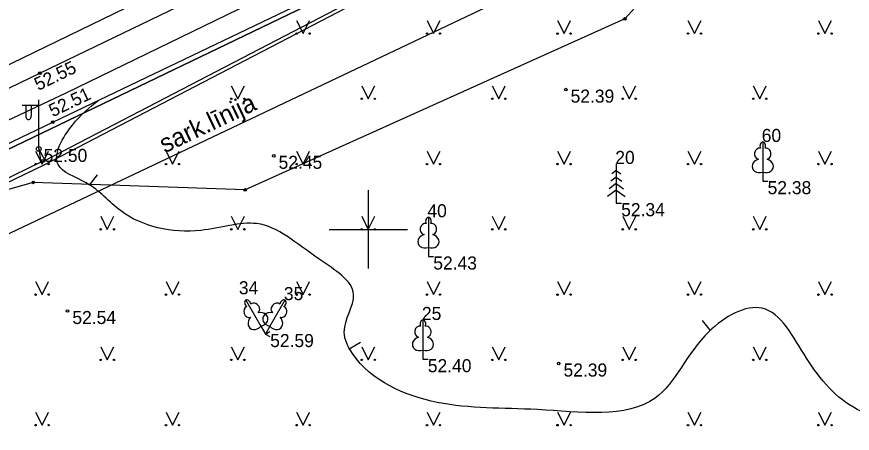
# Model space of a CAD drawing. Extents: x 619806 to 620082, y 405176 to 405386.
# Drawn here: x 619836.53 to 619868.55, y 405292.19 to 405308.14 of the extents above; entities that cross this region are included whole.
import ezdxf

# ---------------------------------------------------------------- set-up
doc = ezdxf.new("R2010")
doc.units = 0
for name, color, linetype in [('24', 7, 'Continuous'), ('APGR_SARK_####_####_#', 7, 'Continuous'), ('APGR_SARK_IZNL_TKST_#', 7, 'Continuous'), ('APGS_ELEM_####_####_#', 7, 'Continuous'), ('APGS_VADP_ZSPR_####_#', 7, 'Continuous'), ('CELI_CMAL_####_####_#', 7, 'Continuous'), ('GEOD_ELEM_####_####_#', 7, 'Continuous'), ('RAMI_UZMR_####_####_#', 7, 'Continuous'), ('RELJ_AATZ_####_TKST_#', 7, 'Continuous'), ('RELJ_ELEM_####_####_#', 7, 'Continuous'), ('RELJ_HORZ_PAMT_####_#', 7, 'Continuous'), ('ROBZ_UZMR_####_####_#', 7, 'Continuous'), ('SAKT_VADP_KABE_####_#', 7, 'Continuous'), ('TERT_DIAM_####_TKST_#', 7, 'Continuous'), ('TERT_ELEM_####_####_#', 7, 'Continuous')]:
    doc.layers.add(name, color=color, linetype=linetype)

msp = doc.modelspace()

# ---------------------------------------------------------------- linework, layer by layer
at = {"layer": '24'}
msp.add_line((619931.837, 405349.12), (619818.193, 405294.391), dxfattribs=at)
at = {"layer": 'APGR_SARK_####_####_#'}
msp.add_lwpolyline([(619818.56, 405291.467), (619964.609, 405360.731), (619976.198, 405343.424)], dxfattribs=at)
at = {"layer": 'APGS_ELEM_####_####_#'}
for p, q in [((619837.373, 405303.082), (619837.373, 405304.965)), ((619837.373, 405304.749), (619836.738, 405304.744)), ((619836.873, 405304.745), (619836.873, 405304.353)), ((619837.083, 405304.747), (619837.083, 405304.353))]:
    msp.add_line(p, q, dxfattribs=at)
msp.add_circle((619837.373, 405303.082), 0.09, dxfattribs=at)
msp.add_ellipse((619836.978, 405304.353), major_axis=(0, 0.151), ratio=0.695971, start_param=1.570796, end_param=4.712389, dxfattribs=at)
at = {"layer": 'APGS_VADP_ZSPR_####_#'}
for points in [[(619961.504, 405361.726), (619961.549, 405360.889), (619955.561, 405357.47), (619948.629, 405353.911), (619942.586, 405351.309), (619934.737, 405347.784), (619926.308, 405343.807), (619921.62, 405341.722), (619914.616, 405338.589), (619904.064, 405332.419), (619892.947, 405327.707), (619882.253, 405322.432), (619872.343, 405318.394), (619866.043, 405315.914), (619858.147, 405313.031), (619849.141, 405308.474), (619837.591, 405302.476), (619829.867, 405298.738), (619827.533, 405297.619), (619826.332, 405294.789), (619825.868, 405290.973), (619826.009, 405290.873), (619827.279, 405290.766)], [(619961.504, 405361.726), (619961.582, 405360.944), (619961.547, 405359.255), (619942.312, 405349.715), (619925.4, 405342.794), (619907.997, 405333.971), (619887.51, 405324.581), (619867.415, 405316.417), (619859.827, 405308.06), (619845.28, 405301.51), (619837.164, 405301.798), (619827.1, 405298.963), (619826.475, 405294.709), (619826.025, 405290.988), (619827.279, 405290.766)], [(619904.019, 405332.565), (619892.911, 405327.951), (619882.359, 405322.589), (619872.341, 405318.531), (619866.186, 405316.142), (619865.74, 405316.62), (619866.013, 405316.067), (619858.137, 405313.192), (619849.107, 405308.602), (619837.621, 405302.637), (619837.373, 405303.082), (619837.457, 405302.572), (619827.49, 405297.724), (619826.22, 405294.811), (619826.787, 405293.322), (619828.348, 405292.084), (619828.449, 405291.159), (619827.279, 405290.766)]]:
    msp.add_lwpolyline(points, dxfattribs=at)
at = {"layer": 'CELI_CMAL_####_####_#'}
for points in [[(619825.042, 405301.626), (619825.997, 405300.736), (619826.865, 405300.888), (619837.411, 405305.982), (619845.924, 405310.094), (619856.691, 405315.252), (619868.203, 405320.761), (619880.848, 405326.828), (619891.162, 405331.79), (619903.487, 405337.685), (619914.792, 405343.079), (619924.282, 405347.611), (619934.782, 405352.643), (619943.391, 405356.735), (619942.998, 405357.499)], [(619901.141, 405301.297), (619895.285, 405291.495), (619886.767, 405291.266), (619876.357, 405290.867), (619868.929, 405290.713), (619868.879, 405291.869), (619865.764, 405291.699), (619865.807, 405290.556), (619863.458, 405290.505), (619853.554, 405290.137), (619841.43, 405289.76), (619840.169, 405289.507), (619836.17, 405288.32), (619833.502, 405287.788), (619826.905, 405297.999), (619827.372, 405299.068), (619837.906, 405304.107), (619846.534, 405308.229), (619856.914, 405313.201), (619868.255, 405318.592), (619880.738, 405324.67), (619889.516, 405328.858), (619904.867, 405336.211)]]:
    msp.add_lwpolyline(points, dxfattribs=at)
at = {"layer": 'GEOD_ELEM_####_####_#'}
for p, q in [((619850, 405301.5), (619850, 405300)), ((619848.5, 405300), (619850, 405300)), ((619850, 405300), (619850, 405298.5)), ((619850, 405300), (619851.5, 405300))]:
    msp.add_line(p, q, dxfattribs=at)
at = {"layer": 'RAMI_UZMR_####_####_#'}
msp.add_lwpolyline([(619874.687, 405324.979), (619926.719, 405349.544), (619966.669, 405369.042), (620021.738, 405292.03), (620049.703, 405275.476), (620026.189, 405242.287), (620012.147, 405222.917), (619996.603, 405200.928), (619989.997, 405199.173), (619982.328, 405199.155), (619922.669, 405233.014), (619882.137, 405255.756), (619859.084, 405268.056), (619820.646, 405290.715), (619813.744, 405295.206), (619820.645, 405298.752)], close=True, dxfattribs=at)
at = {"layer": 'RELJ_ELEM_####_####_#'}
for centre in [(619859.827, 405308.06), (619837.411, 405305.982), (619857.566, 405305.353), (619837.906, 405304.107), (619837.54, 405302.625), (619846.375, 405302.818), (619837.164, 405301.798), (619845.28, 405301.51), (619838.475, 405296.873), (619857.295, 405294.862)]:
    msp.add_circle(centre, 0.05, dxfattribs=at)
at = {"layer": 'RELJ_HORZ_PAMT_####_#'}
for p, q in [((619839.612, 405302.085), (619839.299, 405301.695)), ((619862.791, 405296.51), (619863.106, 405296.122)), ((619849.703, 405295.665), (619849.271, 405295.412))]:
    msp.add_line(p, q, dxfattribs=at)
msp.add_spline([(619896.346, 405293.509), (619894.668, 405293.42), (619893.372, 405292.489), (619891.349, 405293.319), (619886.863, 405295.038), (619884.556, 405295.387), (619880.561, 405295.181), (619877.029, 405296.347), (619875.125, 405295.25), (619872.741, 405292.993), (619868.738, 405293.105), (619866.791, 405295.071), (619865.088, 405296.98), (619863.053, 405296.079), (619860.996, 405293.537), (619856.488, 405293.095), (619852.645, 405293.374), (619849.391, 405295.245), (619849.08, 405296.066), (619849.436, 405297.5), (619848.114, 405298.857), (619845.722, 405300.218), (619843.589, 405299.958), (619840.501, 405300.72), (619839.187, 405301.782), (619838.112, 405302.478), (619838.665, 405303.995), (619839.645, 405304.937)], degree=3, dxfattribs=at)
at = {"layer": 'ROBZ_UZMR_####_####_#'}
msp.add_line((619818.193, 405294.391), (619931.837, 405349.12), dxfattribs=at)
at = {"layer": 'SAKT_VADP_KABE_####_#'}
msp.add_lwpolyline([(619816.151, 405294.73), (619838.42, 405305.23), (619866.149, 405318.697), (619899.278, 405334.929), (619937.202, 405353.635), (619962.924, 405366.289), (619964.424, 405369.208)], dxfattribs=at)
at = {"layer": 'TERT_ELEM_####_####_#'}
for p, q in [((619847.25, 405308), (619847.5, 405307.5)), ((619847.5, 405307.5), (619847.75, 405308)), ((619852.25, 405308), (619852.5, 405307.5)), ((619852.5, 405307.5), (619852.75, 405308)), ((619857.25, 405308), (619857.5, 405307.5)), ((619857.5, 405307.5), (619857.75, 405308)), ((619862.25, 405308), (619862.5, 405307.5)), ((619862.5, 405307.5), (619862.75, 405308)), ((619867.25, 405308), (619867.5, 405307.5)), ((619867.5, 405307.5), (619867.75, 405308)), ((619844.75, 405305.5), (619845, 405305)), ((619845, 405305), (619845.25, 405305.5)), ((619849.75, 405305.5), (619850, 405305)), ((619850, 405305), (619850.25, 405305.5)), ((619854.75, 405305.5), (619855, 405305)), ((619855, 405305), (619855.25, 405305.5)), ((619859.75, 405305.5), (619860, 405305)), ((619860, 405305), (619860.25, 405305.5)), ((619864.75, 405305.5), (619865, 405305)), ((619865, 405305), (619865.25, 405305.5)), ((619837.25, 405303), (619837.5, 405302.5)), ((619837.5, 405302.5), (619837.75, 405303)), ((619842.25, 405303), (619842.5, 405302.5)), ((619842.5, 405302.5), (619842.75, 405303)), ((619847.25, 405303), (619847.5, 405302.5)), ((619847.5, 405302.5), (619847.75, 405303)), ((619852.25, 405303), (619852.5, 405302.5)), ((619852.5, 405302.5), (619852.75, 405303)), ((619857.25, 405303), (619857.5, 405302.5)), ((619857.5, 405302.5), (619857.75, 405303)), ((619862.25, 405303), (619862.5, 405302.5)), ((619862.5, 405302.5), (619862.75, 405303)), ((619867.25, 405303), (619867.5, 405302.5)), ((619867.5, 405302.5), (619867.75, 405303)), ((619859.504, 405302.504), (619859.504, 405301.004)), ((619859.504, 405302.004), (619859.288, 405301.846)), ((619859.504, 405302.254), (619859.328, 405302.126)), ((619859.504, 405302.254), (619859.678, 405302.126)), ((619859.504, 405302.004), (619859.72, 405301.846)), ((619865.115, 405302.194), (619865.115, 405301.847)), ((619859.504, 405301.754), (619859.226, 405301.55)), ((619859.504, 405301.754), (619859.782, 405301.55)), ((619865.115, 405301.847), (619865.315, 405301.847)), ((619859.504, 405301.504), (619859.172, 405301.26)), ((619859.504, 405301.504), (619859.838, 405301.26)), ((619859.504, 405301.004), (619859.704, 405301.004)), ((619839.75, 405300.5), (619840, 405300)), ((619840, 405300), (619840.25, 405300.5)), ((619844.75, 405300.5), (619845, 405300)), ((619845, 405300), (619845.25, 405300.5)), ((619849.75, 405300.5), (619850, 405300)), ((619850, 405300), (619850.25, 405300.5)), ((619854.75, 405300.5), (619855, 405300)), ((619855, 405300), (619855.25, 405300.5)), ((619859.75, 405300.5), (619860, 405300)), ((619860, 405300), (619860.25, 405300.5)), ((619864.75, 405300.5), (619865, 405300)), ((619865, 405300), (619865.25, 405300.5)), ((619852.304, 405299.308), (619852.304, 405298.961)), ((619852.304, 405298.961), (619852.504, 405298.961)), ((619837.25, 405298), (619837.5, 405297.5)), ((619837.5, 405297.5), (619837.75, 405298)), ((619842.25, 405298), (619842.5, 405297.5)), ((619842.5, 405297.5), (619842.75, 405298)), ((619847.25, 405298), (619847.5, 405297.5)), ((619847.5, 405297.5), (619847.75, 405298)), ((619852.25, 405298), (619852.5, 405297.5)), ((619852.5, 405297.5), (619852.75, 405298)), ((619857.25, 405298), (619857.5, 405297.5)), ((619857.5, 405297.5), (619857.75, 405298)), ((619862.25, 405298), (619862.5, 405297.5)), ((619862.5, 405297.5), (619862.75, 405298)), ((619867.25, 405298), (619867.5, 405297.5)), ((619867.5, 405297.5), (619867.75, 405298)), ((619845.882, 405296.291), (619846.055, 405295.99)), ((619846.228, 405296.291), (619846.055, 405295.99)), ((619846.055, 405295.99), (619846.228, 405296.09)), ((619846.055, 405295.99), (619846.228, 405295.89)), ((619839.75, 405295.5), (619840, 405295)), ((619840, 405295), (619840.25, 405295.5)), ((619844.75, 405295.5), (619845, 405295)), ((619845, 405295), (619845.25, 405295.5)), ((619849.75, 405295.5), (619850, 405295)), ((619850, 405295), (619850.25, 405295.5)), ((619852.095, 405295.375), (619852.095, 405295.028)), ((619854.75, 405295.5), (619855, 405295)), ((619855, 405295), (619855.25, 405295.5)), ((619859.75, 405295.5), (619860, 405295)), ((619860, 405295), (619860.25, 405295.5)), ((619864.75, 405295.5), (619865, 405295)), ((619865, 405295), (619865.25, 405295.5)), ((619852.095, 405295.028), (619852.295, 405295.028)), ((619837.25, 405293), (619837.5, 405292.5)), ((619837.5, 405292.5), (619837.75, 405293)), ((619842.25, 405293), (619842.5, 405292.5)), ((619842.5, 405292.5), (619842.75, 405293)), ((619847.25, 405293), (619847.5, 405292.5)), ((619847.5, 405292.5), (619847.75, 405293)), ((619852.25, 405293), (619852.5, 405292.5)), ((619852.5, 405292.5), (619852.75, 405293)), ((619857.25, 405293), (619857.5, 405292.5)), ((619857.5, 405292.5), (619857.75, 405293)), ((619862.25, 405293), (619862.5, 405292.5)), ((619862.5, 405292.5), (619862.75, 405293)), ((619867.25, 405293), (619867.5, 405292.5)), ((619867.5, 405292.5), (619867.75, 405293))]:
    msp.add_line(p, q, dxfattribs=at)
for points in [[(619865.115, 405303.347), (619865.115, 405302.194)], [(619865.205, 405303.115), (619865.204, 405303.116)], [(619852.304, 405300.461), (619852.304, 405299.308)], [(619852.394, 405300.229), (619852.393, 405300.23)], [(619845.305, 405297.289), (619845.882, 405296.291)], [(619846.805, 405297.289), (619846.228, 405296.291)], [(619845.499, 405297.133), (619845.497, 405297.133)], [(619846.766, 405297.043), (619846.766, 405297.044)], [(619852.095, 405296.528), (619852.095, 405295.375)], [(619852.185, 405296.296), (619852.184, 405296.297)]]:
    msp.add_lwpolyline(points, dxfattribs=at)
for centre, radius in [((619847.25, 405307.5), 0.028), ((619847.75, 405307.5), 0.0263), ((619852.25, 405307.5), 0.028), ((619852.75, 405307.5), 0.0263), ((619857.25, 405307.5), 0.028), ((619857.75, 405307.5), 0.0263), ((619862.25, 405307.5), 0.028), ((619862.75, 405307.5), 0.0263), ((619867.25, 405307.5), 0.028), ((619867.75, 405307.5), 0.0263), ((619844.75, 405305), 0.028), ((619845.25, 405305), 0.0263), ((619849.75, 405305), 0.028), ((619850.25, 405305), 0.0263), ((619854.75, 405305), 0.028), ((619855.25, 405305), 0.0263), ((619859.75, 405305), 0.028), ((619860.25, 405305), 0.0263), ((619864.75, 405305), 0.028), ((619865.25, 405305), 0.0263), ((619837.25, 405302.5), 0.028), ((619837.75, 405302.5), 0.0263), ((619842.25, 405302.5), 0.028), ((619842.75, 405302.5), 0.0263), ((619847.25, 405302.5), 0.028), ((619847.75, 405302.5), 0.0263), ((619852.25, 405302.5), 0.028), ((619852.75, 405302.5), 0.0263), ((619857.25, 405302.5), 0.028), ((619857.75, 405302.5), 0.0263), ((619862.25, 405302.5), 0.028), ((619862.75, 405302.5), 0.0263), ((619867.25, 405302.5), 0.028), ((619867.75, 405302.5), 0.0263), ((619839.75, 405300), 0.028), ((619840.25, 405300), 0.0263), ((619844.75, 405300), 0.028), ((619845.25, 405300), 0.0263), ((619849.75, 405300), 0.028), ((619850.25, 405300), 0.0263), ((619854.75, 405300), 0.028), ((619855.25, 405300), 0.0263), ((619859.75, 405300), 0.028), ((619860.25, 405300), 0.0263), ((619864.75, 405300), 0.028), ((619865.25, 405300), 0.0263), ((619837.25, 405297.5), 0.028), ((619837.75, 405297.5), 0.0263), ((619842.25, 405297.5), 0.028), ((619842.75, 405297.5), 0.0263), ((619847.25, 405297.5), 0.028), ((619847.75, 405297.5), 0.0263), ((619852.25, 405297.5), 0.028), ((619852.75, 405297.5), 0.0263), ((619857.25, 405297.5), 0.028), ((619857.75, 405297.5), 0.0263), ((619862.25, 405297.5), 0.028), ((619862.75, 405297.5), 0.0263), ((619867.25, 405297.5), 0.028), ((619867.75, 405297.5), 0.0263), ((619839.75, 405295), 0.028), ((619840.25, 405295), 0.0263), ((619844.75, 405295), 0.028), ((619845.25, 405295), 0.0263), ((619849.75, 405295), 0.028), ((619850.25, 405295), 0.0263), ((619854.75, 405295), 0.028), ((619855.25, 405295), 0.0263), ((619859.75, 405295), 0.028), ((619860.25, 405295), 0.0263), ((619864.75, 405295), 0.028), ((619865.25, 405295), 0.0263), ((619837.25, 405292.5), 0.028), ((619837.75, 405292.5), 0.0263), ((619842.25, 405292.5), 0.028), ((619842.75, 405292.5), 0.0263), ((619847.25, 405292.5), 0.028), ((619847.75, 405292.5), 0.0263), ((619852.25, 405292.5), 0.028), ((619852.75, 405292.5), 0.0263), ((619857.25, 405292.5), 0.028), ((619857.75, 405292.5), 0.0263), ((619862.25, 405292.5), 0.028), ((619862.75, 405292.5), 0.0263), ((619867.25, 405292.5), 0.028), ((619867.75, 405292.5), 0.0263)]:
    msp.add_circle(centre, radius, dxfattribs=at)
for centre, major_axis, ratio, start_param, end_param in [((619865.115, 405303.197), (0, -0.15), 0.707107, 3.14537, 5.287485), ((619865.115, 405303.197), (0, -0.15), 0.707107, 0.995701, 3.137816), ((619864.987, 405302.902), (-0.039, -0.212), 0.861323, 3.141593, 6.283185), ((619865.243, 405302.902), (0.039, -0.212), 0.861323, 0, 3.141593), ((619865.025, 405302.44), (0.307, 0.095), 0.814445, 1.570796, 4.752015), ((619865.205, 405302.44), (-0.307, 0.095), 0.814445, 1.531171, 4.712389), ((619852.304, 405300.311), (0, -0.15), 0.707107, 3.14537, 5.287485), ((619852.304, 405300.311), (0, -0.15), 0.707107, 0.995701, 3.137816), ((619852.176, 405300.016), (-0.039, -0.212), 0.861323, 3.141593, 6.283185), ((619852.432, 405300.016), (0.039, -0.212), 0.861323, 0, 3.141593), ((619852.214, 405299.554), (0.307, 0.095), 0.814445, 1.570796, 4.752015), ((619852.394, 405299.554), (-0.307, 0.095), 0.814445, 1.531171, 4.712389), ((619845.38, 405297.159), (0.075, -0.13), 0.707107, 3.14537, 5.287485), ((619845.38, 405297.159), (0.075, -0.13), 0.707107, 0.995701, 3.137816), ((619845.639, 405296.968), (0.14, -0.165), 0.861323, 0, 3.141593), ((619846.471, 405296.968), (-0.14, -0.165), 0.861323, 3.141593, 6.283185), ((619846.73, 405297.159), (-0.075, -0.13), 0.707107, 3.14537, 5.287485), ((619846.73, 405297.159), (-0.075, -0.13), 0.707107, 0.995701, 3.137816), ((619845.416, 405296.84), (0.073, -0.203), 0.861323, 3.141593, 6.283185), ((619845.836, 405296.548), (-0.313, -0.071), 0.814445, 1.531171, 4.712389), ((619846.274, 405296.548), (0.313, -0.071), 0.814445, 1.570796, 4.752015), ((619846.694, 405296.84), (-0.073, -0.203), 0.861323, 0, 3.141593), ((619845.681, 405296.459), (0.218, 0.236), 0.814445, 1.570796, 4.752015), ((619846.429, 405296.459), (-0.218, 0.236), 0.814445, 1.531171, 4.712389), ((619852.095, 405296.378), (0, -0.15), 0.707107, 3.14537, 5.287485), ((619852.095, 405296.378), (0, -0.15), 0.707107, 0.995701, 3.137816), ((619851.967, 405296.083), (-0.039, -0.212), 0.861323, 3.141593, 6.283185), ((619852.223, 405296.083), (0.039, -0.212), 0.861323, 0, 3.141593), ((619852.005, 405295.621), (0.307, 0.095), 0.814445, 1.570796, 4.752015), ((619852.185, 405295.621), (-0.307, 0.095), 0.814445, 1.531171, 4.712389)]:
    msp.add_ellipse(centre, major_axis=major_axis, ratio=ratio, start_param=start_param, end_param=end_param, dxfattribs=at)

# ---------------------------------------------------------------- texts
at = {"layer": 'APGR_SARK_IZNL_TKST_#'}
msp.add_text('sark.līnija', height=0.7, rotation=25.3727, dxfattribs=at).set_placement((619842.2, 405302.911))
at = {"layer": 'RELJ_AATZ_####_TKST_#'}
for s, rotation, p in [(' 52.55', 25.7817, (619837.187, 405305.22)), (' 52.51', 25.536, (619837.741, 405304.21))]:
    msp.add_text(s, height=0.5, rotation=rotation, dxfattribs=at).set_placement(p)
for s, p in [(' 52.39', (619857.566, 405304.853)), (' 52.50', (619837.373, 405302.582)), (' 52.45', (619846.375, 405302.318)), (' 52.38', (619865.115, 405301.347)), (' 52.34', (619859.504, 405300.504)), (' 52.43', (619852.304, 405298.461)), (' 52.54', (619838.475, 405296.373)), (' 52.59', (619846.055, 405295.49)), (' 52.40', (619852.095, 405294.528)), (' 52.39', (619857.295, 405294.362))]:
    msp.add_text(s, height=0.5, dxfattribs=at).set_placement(p)
at = {"layer": 'TERT_DIAM_####_TKST_#'}
for s, p in [(' 60', (619864.89, 405303.347)), (' 20', (619859.279, 405302.504)), (' 40', (619852.079, 405300.461)), (' 34', (619844.855, 405297.514)), (' 35', (619846.58, 405297.289)), (' 25', (619851.87, 405296.528))]:
    msp.add_text(s, height=0.5, dxfattribs=at).set_placement(p)

doc.saveas('drawing.dxf')
